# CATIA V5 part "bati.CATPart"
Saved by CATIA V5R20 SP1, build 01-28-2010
Part number: bati
Bounding box of the stored display mesh (mm): x 0 to 650, y -560 to 1100, z -25 to 800
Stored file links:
  C:\Users\Nicolas\Desktop\beta\bati.CATPart
  C:\Users\Nicolas\Desktop\beta\Product1.CATProduct
  C:\Users\Nicolas\Desktop\beta\Squelette.CATPart
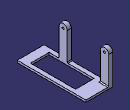
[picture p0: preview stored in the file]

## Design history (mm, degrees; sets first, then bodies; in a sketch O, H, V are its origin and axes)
Set1
  Point1: linked copy from another document
  Point2: linked copy from another document
  Plane1: linked copy from another document
Body1 (main body)
  Sketch1 on yz-plane, origin (0, 0, 0), H (0, 1, 0), V (0, 0, 1)
    line L1 (-560, -25) -> (1100, -25)
    line L2 (1100, -25) -> (1100, 700)
    line L3 (900, 25) -> (100, 25)
    line L4 (-560, 25) -> (-560, -25)
    point P3 (1100, 700)
    point P5 (1100, 700)
    arc A1 centre (1000, 700) radius 100 from (1100, 700) to (900, 700) ccw
    point P6 (1000, 700)
    line L5 (900, 700) -> (900, 25)
    line L6 (100, 25) -> (100, 700)
    point P11 (-100, 700)
    line L7 (-100, 700) -> (-100, 25)
    point P12 (-100, 25)
    arc A2 centre (0, 700) radius 100 from (100, 700) to (-100, 700) ccw
    point P13 (0, 700)
    reference projected point E1 (0, 700) from Point1
    reference projected point E2 (1000, 700) from Point2
    line L8 (-100, 25) -> (-560, 25)
    point P14 (-100, 700)
    distance L1 L3 = 50
    distance L5 L2 = 200
    distance L7 L6 = 200
    length L8 = 460
    horizontal: L1 H, L3 H, L8 H
    vertical: L2 V, L4 V, L7 V, L6 V, L5 V
    coincidence: P12 L3, P11 A2, P13 E1, P6 E2, L3 L8, P3 P5, L7 P14, P11 P14
    tangency: A2 L7, L6 A2, A1 L5, L2 A1
    symmetry: L1 L3 H
  Pad1: profile Sketch1, direction (1, 0, 0), up to Plane1
  Sketch2 on end face of Pad1, origin (100, 1000, 700), H (0, 1, 0), V (0, 0, 1)
    point P1 (0, 0)
    reference projected point E1 (0, 0) from Point2
    coincidence: E1 P1
  Hole1: placed by Sketch2, at (100, 1000, 700) direction (-1, 0, 0), diameter 50, through (limit type 6)
  Sketch3 on end face of Pad1, origin (100, 0, 700), H (0, 1, 0), V (0, 0, 1)
    point P1 (0, 0)
    reference projected point E1 (0, 0) from Point1
    coincidence: E1 P1
  Hole2: placed by Sketch3, at (100, 0, 700) direction (-1, 0, 0), diameter 50, through (limit type 6)
  Sketch4 on end face of Pad1, origin (100, 0, 0), H (0, 1, 0), V (0, 0, 1)
    line L1 (-560, 25) -> (-340, 25)
    line L2 (-340, 25) -> (-340, -25)
    line L3 (-340, -25) -> (-560, -25)
    line L4 (-560, -25) -> (-560, 25)
    line L5 (750, 25) -> (1100, 25)
    line L6 (1100, 25) -> (1100, -25)
    line L7 (1100, -25) -> (750, -25)
    line L8 (750, -25) -> (750, 25)
    point P7 (1100, -25)
    reference projected line E1 (-457.676, -25) -> (1100, -25) from edge [face of Pad1 from Sketch1.L1 | end face of Pad1]
    reference projected line E2 (-100, 25) -> (-457.676, 25) from edge [face of Pad1 from Sketch1.L8 | end face of Pad1]
    reference projected line E3 (900, 25) -> (100, 25) from edge [face of Pad1 from Sketch1.L3 | end face of Pad1]
    reference projected line E4 (-560, 25) -> (-560, -25) from edge [face of Pad1 from Sketch1.L4 | end face of Pad1]
    reference projected line E5 (-560, 25) -> (-560, -25) from edge [face of Pad1 from Sketch1.L4 | end face of Pad1]
    reference projected line E6 (1100, -25) -> (1100, 700) from edge [face of Pad1 from Sketch1.L2 | end face of Pad1]
    reference projected line E7 (1100, -25) -> (1100, 700) from edge [face of Pad1 from Sketch1.L2 | end face of Pad1]
    distance L2 E4 = 220
    distance L8 E6 = 350
    horizontal: L1 H, L3 H, L5 H, L7 H
    vertical: L2 V, L4 V, L6 V, L8 V
    coincidence: P7 L3, L3 E1, L1 E2, L5 E3, L4 E5, L6 E7
  Pad2: profile Sketch4, direction (1, 0, 0), length 450
  Sketch5 on end face of Pad2, origin (550, 0, 0), H (0, 1, 0), V (0, 0, 1)
    line L1 (-560, 25) -> (1100, 25)
    line L2 (1100, 25) -> (1100, -25)
    line L3 (1100, -25) -> (-560, -25)
    line L4 (-560, -25) -> (-560, 25)
    reference projected line E1 (1358.2599, 25) -> (900, 25) from edge [face of Pad2 from Sketch4.L5 | end face of Pad2]
    reference projected line E2 (1100, -25) -> (1100, 25) from edge [face of Pad2 from Sketch4.L6 | end face of Pad2]
    reference projected line E3 (900, -25) -> (1358.2599, -25) from edge [face of Pad2 from Sketch4.L7 | end face of Pad2]
    reference projected line E4 (-560, 25) -> (-560, -25) from edge [face of Pad2 from Sketch4.L4 | end face of Pad2]
    horizontal: L1 H, L3 H
    vertical: L2 V, L4 V
    coincidence: E1 L1, L2 E2, L3 E3, L4 E4
  Pad3: profile Sketch5, direction (1, 0, 0), length 100
  Chamfer1: length 20, angle 45, on edge [face of Pad3 | face of Pad1 from Sketch1.L7]; edge [face of Pad1 from Sketch1.L6 | face of Pad1 from Sketch1.L3]; edge [face of Pad1 from Sketch1.L3 | face of Pad1 from Sketch1.L5]; edge [end face of Pad1 | face of Pad3]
